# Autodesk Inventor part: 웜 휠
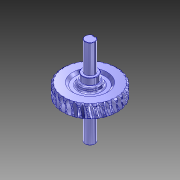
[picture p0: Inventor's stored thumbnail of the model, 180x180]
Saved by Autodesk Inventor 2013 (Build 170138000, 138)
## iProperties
Created: 2013-01
Part Number: 웜 휠
Material: 탄소강
Document SubType Name: Modeling
Designer: 한국산업디자인학원[gmhk.co.kr]
Categories: <?xml version="1.0" encoding="UTF-16"?> <MemberInstance><Categories><FamilyTemplate><FamilyTemplateParameter ValueType="xs:double" Id="1" ObjectReferenceKey="da
Density: 7.87 g/cm^3
Mass: 6989.44 g
Surface Area: 1041.74 cm^2
Volume: 888.112 cm^3
CustomPartVersion: 1
Author: 한국산업디자인학원[gmhk.co.kr]
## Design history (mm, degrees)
body "Solid1"
node "톱니 평면"
sketch "기본 본체 스케치"
  geometry: L1 (0, -14)-(0, 14) reference; L2 (0, 20)-(77.639, 20); L3 (77.639, 20)-(82.5, 15.652); L4 (-10, 0)-(60, 0) reference; L5 (82.5, 15.652)-(82.5, -15.652); L6 (0, -20)-(77.639, -20); L7 (0, 20)-(0, -20); L8 (77.639, -20)-(82.5, -15.652); C1 r 20 at (100, 0)
  constraints: 14 end point, 3 symmetric about line, 2 perpendicular, 2 point on line, 1 centre point, 1 collinear
  dimensions: "d50" = 41.8103 deg angle of L3 L2 (= da_fi); "d87" = 165 diameter of L5 L1 (= da_dae); "d89" = 40 diameter of C1 (= 2 x da_aw - da_da); "d92" = 40 distance of L2.start L6.start (= da_b); "d93" = 100 distance from line of C1.centre L7 (= da_aw)
revolve "기본 본체" stored, may be unused: angle "d35" = 90 deg
revolve "기본 본체2" stored, may be unused: angle "d90" = 90 deg
workplane "Work Plane13"
revolve "톱니" stored, may be unused: angle "d43" = 90 deg
pattern_circular "톱니 패턴" dims angle "d46" = 360 deg
workplane "Work Plane14"
workplane "Work Plane15"
revolve "회전6" stored, may be unused: angle "d97" = 90 deg
revolve "회전7" stored, may be unused: angle "d104" = 90 deg
fillet "모깎기1" dims "d105" = 5
chamfer "모따기1" distance "d106" = 1; stored, may be unused: second distance "d107" = 2, angle "d108" = 45 deg
node "작업 평면16"
sketch "스케치11"
  geometry: L1 (-14, 43)-(14, 43) reference; L2 (4, 43)-(4, 22); L3 (-4, 22)-(-4, 43); A1 r 4 centre (0, 22) between (-4, 22) and (4, 22); 2 further points
  constraints: 4 end point, 2 perpendicular, 2 point on circle, 2 point on line, 2 tangent, 1 centre point, 1 midpoint, 1 vertical alignment
  dimensions: "d109" = 8 distance between parallel lines of L2 L3; "d110" = 25 dimension on A1 L1
extrude "돌출1" cut sketch "스케치11" distance "d111" = 4; taper "d112" = 0 deg
mirror "대칭1"
sketch "톱니 스케치"
  geometry: L1 (10, 5.301)-(10, -5.301) reference; L2 (-32.842, 0)-(-12.948, 0) reference; L3 (-90, 6.896)-(-90, -6.896); L4 (-90, -6.896)-(-71, -6.896); L5 (-71, -6.896)-(-59, -2.529); L6 (-59, -2.529)-(-59, 0); L7 (-59, 2.529)-(-71, 6.896); L8 (-71, 6.896)-(-90, 6.896); L9 (-59, 2.529)-(-59, 0); L10 (-65, 0)-(-65, -4.712)
  constraints: 16 end point, 4 perpendicular, 3 equal length, 2 point on line, 1 midpoint, 1 parallel, 1 vertical
  dimensions: "d38" = 100 distance between parallel lines of L1 L3 (= da_aw); "d39" = 20 deg angle of L7 L8 (= da_alfat); "d40" = 19 distance of L7.end L3.start (= 0.5 x da_df1); "d41" = 25 distance between parallel lines of L3 L10 (= 0.5 x da_d1); "d42" = 4.71239 distance of L10.start L10.end (= 0.3 x da_px)
sketch "Sketch8"
  geometry: C1 r 77.639 at (0, 0) reference; C2 r 75 at (0, 0)
  constraints: 1 centre point, 1 coincident
  dimensions: "d77" = 150 diameter of C2 (= da_dw)
body "Srf1"
sketch "스케치9"
  geometry: L1 (-74.283, 20)-(-74.054, 20) reference; L2 (-74.054, 20)-(-74.261, 20) reference; L3 (-74.261, 20)-(-75.727, 20) reference; L4 (-77.355, 20)-(-75.727, 20) reference; L5 (-77.355, 20)-(-77.106, 20) reference; L6 (-77.106, 20)-(-76.222, 20) reference; L7 (-76.222, 20)-(-77.633, 20) reference; L8 (-77.045, 20)-(-77.633, 20) reference; L9 (-77.045, 20)-(-76.789, 20) reference; L10 (-76.789, 20)-(-74.852, 20) reference; L11 (-74.852, 20)-(-76.145, 20) reference; L12 (-73.369, 20)-(-76.145, 20) reference; L13 (-73.369, 20)-(-73.116, 20) reference; L14 (-73.116, 20)-(-70.211, 20) reference; L15 (-70.211, 20)-(-71.33, 20) reference; L16 (-66.486, 20)-(-71.33, 20) reference; L17 (-66.486, 20)-(-66.247, 20) reference; L18 (-66.247, 20)-(-62.501, 20) reference; L19 (-62.501, 20)-(-63.397, 20) reference; L20 (-56.697, 20)-(-63.397, 20) reference; L21 (-56.697, 20)-(-56.483, 20) reference; L22 (-56.483, 20)-(-52.059, 20) reference; L23 (-52.059, 20)-(-52.693, 20) reference; L24 (-44.431, 20)-(-52.693, 20) reference; L25 (-44.431, 20)-(-44.25, 20) reference; L26 (-44.25, 20)-(-39.342, 20) reference; L27 (-39.342, 20)-(-39.687, 20) reference; L28 (-30.222, 20)-(-39.687, 20) reference; L29 (-30.222, 20)-(-30.084, 20) reference; L30 (-30.084, 20)-(-24.906, 20) reference; L31 (-24.906, 20)-(-24.945, 20) reference; L32 (-14.693, 20)-(-24.945, 20) reference; L33 (-14.693, 20)-(-14.602, 20) reference; L34 (-14.602, 20)-(-9.381, 20) reference; L35 (-9.381, 20)-(-9.114, 20) reference; L36 (1.479, 20)-(-9.114, 20) reference; L37 (1.479, 20)-(1.517, 20) reference; L38 (1.517, 20)-(6.554, 20) reference; L39 (6.554, 20)-(7.116, 20) reference; L40 (17.586, 20)-(7.116, 20) reference; L41 (17.586, 20)-(17.571, 20) reference; L42 (17.571, 20)-(22.202, 20) reference; L43 (22.202, 20)-(23.034, 20) reference; L44 (32.924, 20)-(23.034, 20) reference; L45 (32.924, 20)-(32.856, 20) reference; L46 (32.856, 20)-(36.88, 20) reference; L47 (36.88, 20)-(37.946, 20) reference; L48 (46.823, 20)-(37.946, 20) reference; L49 (46.823, 20)-(46.705, 20) reference; L50 (46.705, 20)-(49.946, 20) reference; L51 (49.946, 20)-(51.2, 20) reference; L52 (58.676, 20)-(51.2, 20) reference; L53 (58.676, 20)-(58.514, 20) reference; L54 (58.514, 20)-(60.83, 20) reference; L55 (60.83, 20)-(62.216, 20) reference; L56 (67.965, 20)-(62.216, 20) reference; L57 (67.965, 20)-(67.764, 20) reference; L58 (67.764, 20)-(69.055, 20) reference; L59 (69.055, 20)-(70.512, 20) reference; L60 (74.283, 20)-(70.512, 20) reference; L61 (74.283, 20)-(74.054, 20) reference; L62 (74.054, 20)-(74.261, 20) reference; L63 (74.261, 20)-(75.727, 20) reference; L64 (77.355, 20)-(75.727, 20) reference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
  constraints: 8 end point, 3 point on line, 2 perpendicular, 1 parallel
  dimensions: "d94" = 90 diameter of L122.end L121; "d95" = 135 deg angle of L123 L122; "d96" = 13 distance from line of L121.start L122
node "투영된 루프1"
sketch "스케치10"
  geometry: L1 (45, 13)-(-45, 13) reference; L2 (0, 13)-(0, 133); L3 (0, 133)-(-15, 133); L4 (-15, 133)-(-15, 47); L5 (-15, 47)-(-22.5, 47); L6 (-22.5, 47)-(-22.5, 28); L7 (-22.5, 28)-(-30, 28); L8 (-30, 28)-(-30, 13); L9 (30, 47)-(-30, 47) reference; 1 further point
  constraints: 14 end point, 4 parallel, 3 perpendicular, 1 collinear, 1 midpoint, 1 point on line
  dimensions: "d99" = 30 diameter of L4 L2; "d100" = 45 diameter of L6 L2; "d101" = 60 diameter of L8 L2; "d102" = 15 distance between parallel lines of L7 L1; "d103" = 120 distance of L2.start L2.end
node "참조1"
feature "피치 지름" dims "d78" = 40 (= da_b), "d79" = 0
other parameters: "da_aw" = 100 [user parameter; used in 5 equation terms], "da_fi" = 41.8103 deg [user parameter; used in 1 equation term], "da_b" = 40 [user parameter; used in 2 equation terms], "da_df" = 138 [user parameter], "da_beta" = 1.97396 [user parameter; used in 1 equation term], "da_alfat" = 20 deg [user parameter; used in 1 equation term], "da_df1" = 38 [user parameter; used in 1 equation term], "da_px" = 90 deg [user parameter; used in 1 equation term], "d37" = -1.97396 (computed from da_rightdir, da_beta), "d69" = 0, "d73" = 0, "d75" = 6 deg (computed from da_z), "da_dw" = 150 [user parameter; used in 1 equation term], "da_rightdir" = 0 [user parameter; used in 1 equation term], "d80" = 0, "d81" = 0, "d82" = 0, "d83" = 6 deg (computed from da_z), "d84" = 0, "d85" = 180 deg, "da_dae" = 165 [user parameter; used in 1 equation term]
